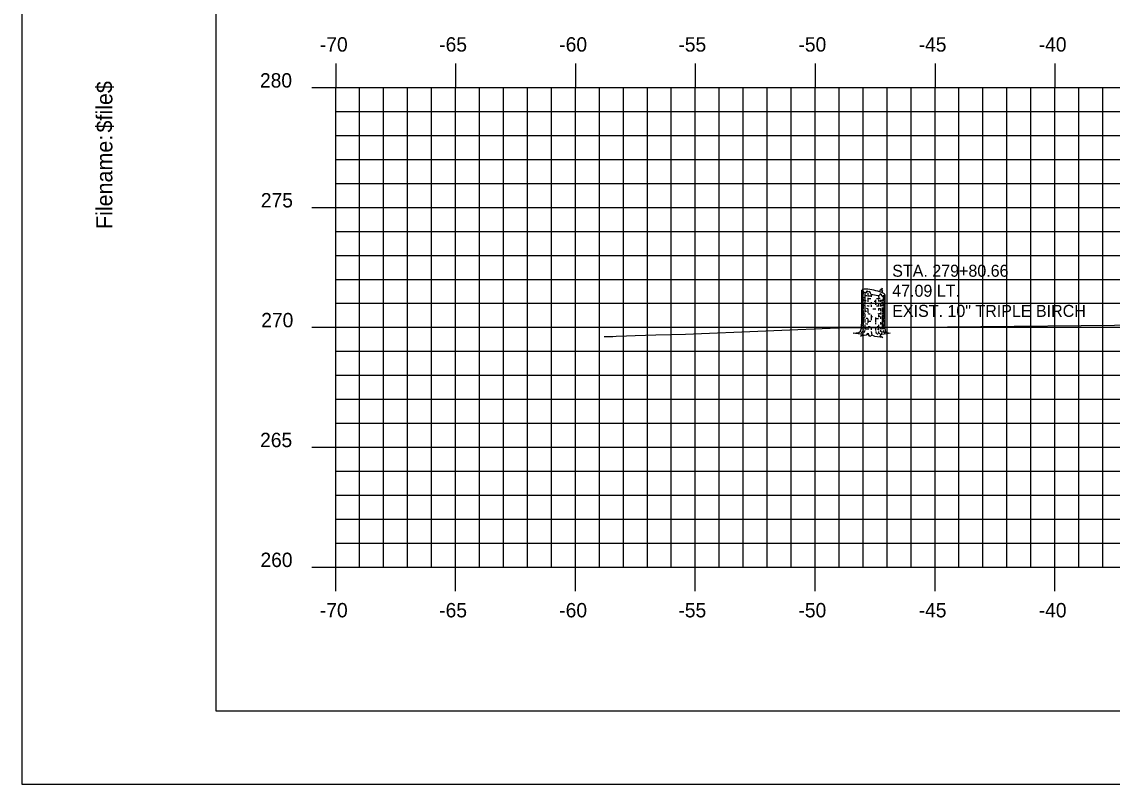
# Model space of a CAD drawing. Extents: x 855121 to 855291, y 366268 to 366378.
# Drawn here: x 855121.35 to 855166.83, y 366268.18 to 366299.98 of the extents above; entities that cross this region are included whole.
import ezdxf

# ---------------------------------------------------------------- set-up
doc = ezdxf.new("R2010")
doc.units = 0
for name, color, linetype in [('BORDER', 7, 'Continuous'), ('D_Text_Monospaced', 7, 'Continuous'), ('H_V ANNOTATION', 7, 'Continuous'), ('MAJOR', 7, 'Continuous'), ('MINOR', 7, 'Continuous'), ('PLOT BOUNDARY', 7, 'Continuous'), ('S_Roadway_Centerline', 7, 'Continuous'), ('S_Trees_Decid_NonPay', 7, 'Continuous')]:
    doc.layers.add(name, color=color, linetype=linetype)

msp = doc.modelspace()

# ---------------------------------------------------------------- linework, layer by layer
at = {"layer": 'BORDER'}
for p, q in [((855129.442, 366376.236), (855129.442, 366271.236)), ((855129.442, 366271.236), (855289.442, 366271.236))]:
    msp.add_line(p, q, dxfattribs=at)
at = {"layer": 'MAJOR'}
for p, q in [((855134.442, 366298.238), (855134.442, 366297.236)), ((855139.442, 366298.238), (855139.442, 366297.236)), ((855144.442, 366298.238), (855144.442, 366297.236)), ((855149.442, 366298.238), (855149.442, 366297.236)), ((855154.442, 366298.238), (855154.442, 366297.236)), ((855159.442, 366298.238), (855159.442, 366297.236)), ((855164.442, 366298.238), (855164.442, 366297.236)), ((855133.44, 366297.236), (855134.442, 366297.236)), ((855134.442, 366297.236), (855274.442, 366297.236)), ((855134.442, 366277.236), (855134.442, 366297.236)), ((855134.442, 366277.236), (855134.442, 366297.236)), ((855134.442, 366297.236), (855274.442, 366297.236)), ((855139.442, 366277.236), (855139.442, 366297.236)), ((855144.442, 366277.236), (855144.442, 366297.236)), ((855149.442, 366277.236), (855149.442, 366297.236)), ((855154.442, 366277.236), (855154.442, 366297.236)), ((855159.442, 366277.236), (855159.442, 366297.236)), ((855164.442, 366277.236), (855164.442, 366297.236)), ((855133.44, 366292.236), (855134.442, 366292.236)), ((855134.442, 366292.236), (855274.442, 366292.236)), ((855133.44, 366287.236), (855134.442, 366287.236)), ((855134.442, 366287.236), (855274.442, 366287.236)), ((855133.44, 366282.236), (855134.442, 366282.236)), ((855134.442, 366282.236), (855274.442, 366282.236)), ((855133.44, 366277.236), (855134.442, 366277.236)), ((855134.442, 366277.236), (855274.442, 366277.236)), ((855134.442, 366277.236), (855274.442, 366277.236)), ((855134.442, 366276.234), (855134.442, 366277.236)), ((855139.442, 366276.234), (855139.442, 366277.236)), ((855144.442, 366276.234), (855144.442, 366277.236)), ((855149.442, 366276.234), (855149.442, 366277.236)), ((855154.442, 366276.234), (855154.442, 366277.236)), ((855159.442, 366276.234), (855159.442, 366277.236)), ((855164.442, 366276.234), (855164.442, 366277.236))]:
    msp.add_line(p, q, dxfattribs=at)
at = {"layer": 'MINOR'}
for p, q in [((855134.442, 366277.236), (855134.442, 366297.236)), ((855135.442, 366277.236), (855135.442, 366297.236)), ((855136.442, 366277.236), (855136.442, 366297.236)), ((855137.442, 366277.236), (855137.442, 366297.236)), ((855138.442, 366277.236), (855138.442, 366297.236)), ((855140.442, 366277.236), (855140.442, 366297.236)), ((855141.442, 366277.236), (855141.442, 366297.236)), ((855142.442, 366277.236), (855142.442, 366297.236)), ((855143.442, 366277.236), (855143.442, 366297.236)), ((855145.442, 366277.236), (855145.442, 366297.236)), ((855146.442, 366277.236), (855146.442, 366297.236)), ((855147.442, 366277.236), (855147.442, 366297.236)), ((855148.442, 366277.236), (855148.442, 366297.236)), ((855150.442, 366277.236), (855150.442, 366297.236)), ((855151.442, 366277.236), (855151.442, 366297.236)), ((855152.442, 366277.236), (855152.442, 366297.236)), ((855153.442, 366277.236), (855153.442, 366297.236)), ((855155.442, 366277.236), (855155.442, 366297.236)), ((855156.442, 366277.236), (855156.442, 366297.236)), ((855157.442, 366277.236), (855157.442, 366297.236)), ((855158.442, 366277.236), (855158.442, 366297.236)), ((855160.442, 366277.236), (855160.442, 366297.236)), ((855161.442, 366277.236), (855161.442, 366297.236)), ((855162.442, 366277.236), (855162.442, 366297.236)), ((855163.442, 366277.236), (855163.442, 366297.236)), ((855165.442, 366277.236), (855165.442, 366297.236)), ((855166.442, 366277.236), (855166.442, 366297.236)), ((855134.442, 366296.236), (855274.442, 366296.236)), ((855134.442, 366296.236), (855135.444, 366296.236)), ((855134.442, 366295.236), (855274.442, 366295.236)), ((855134.442, 366295.236), (855135.444, 366295.236)), ((855134.442, 366294.236), (855274.442, 366294.236)), ((855134.442, 366294.236), (855135.444, 366294.236)), ((855134.442, 366293.236), (855274.442, 366293.236)), ((855134.442, 366293.236), (855135.444, 366293.236)), ((855134.442, 366291.236), (855274.442, 366291.236)), ((855134.442, 366291.236), (855135.444, 366291.236)), ((855134.442, 366290.236), (855274.442, 366290.236)), ((855134.442, 366290.236), (855135.444, 366290.236)), ((855134.442, 366289.236), (855274.442, 366289.236)), ((855134.442, 366289.236), (855135.444, 366289.236)), ((855134.442, 366288.236), (855274.442, 366288.236)), ((855134.442, 366288.236), (855135.444, 366288.236)), ((855134.442, 366286.236), (855274.442, 366286.236)), ((855134.442, 366286.236), (855135.444, 366286.236)), ((855134.442, 366285.236), (855274.442, 366285.236)), ((855134.442, 366285.236), (855135.444, 366285.236)), ((855134.442, 366284.236), (855274.442, 366284.236)), ((855134.442, 366284.236), (855135.444, 366284.236)), ((855134.442, 366283.236), (855274.442, 366283.236)), ((855134.442, 366283.236), (855135.444, 366283.236)), ((855134.442, 366281.236), (855274.442, 366281.236)), ((855134.442, 366281.236), (855135.444, 366281.236)), ((855134.442, 366280.236), (855274.442, 366280.236)), ((855134.442, 366280.236), (855135.444, 366280.236)), ((855134.442, 366279.236), (855274.442, 366279.236)), ((855134.442, 366279.236), (855135.444, 366279.236)), ((855134.442, 366278.236), (855274.442, 366278.236)), ((855134.442, 366278.236), (855135.444, 366278.236))]:
    msp.add_line(p, q, dxfattribs=at)
at = {"layer": 'PLOT BOUNDARY'}
msp.add_lwpolyline([(855121.349, 366268.177), (855291.349, 366268.177), (855291.349, 366378.177), (855121.349, 366378.177)], close=True, dxfattribs=at)
at = {"layer": 'S_Roadway_Centerline'}
msp.add_lwpolyline([(855145.639, 366286.847), (855145.792, 366286.851), (855146.004, 366286.857), (855146.141, 366286.862), (855146.573, 366286.879), (855146.934, 366286.894), (855147.8, 366286.924), (855149.04, 366286.949), (855155.731, 366287.224), (855156.269, 366287.225), (855156.866, 366287.226), (855157.182, 366287.226), (855171.097, 366287.369)], dxfattribs=at)
at = {"layer": 'S_Trees_Decid_NonPay'}
for p, q in [((855156.448, 366288.732), (855156.448, 366288.637)), ((855156.448, 366288.411), (855156.448, 366288.328)), ((855156.516, 366288.645), (855156.516, 366288.344)), ((855156.635, 366288.662), (855156.635, 366288.514)), ((855156.635, 366288.466), (855156.635, 366288.297)), ((855156.782, 366288.616), (855156.782, 366288.509)), ((855156.962, 366288.38), (855156.962, 366288.18)), ((855157.079, 366288.564), (855157.079, 366288.485)), ((855157.079, 366288.398), (855157.079, 366288.314)), ((855157.166, 366288.38), (855157.166, 366288.293)), ((855157.236, 366288.553), (855157.236, 366288.501)), ((855157.236, 366288.398), (855157.236, 366288.316)), ((855157.279, 366288.558), (855157.279, 366288.341)), ((855157.306, 366288.488), (855157.306, 366288.406)), ((855156.448, 366288.258), (855156.448, 366288.007)), ((855156.448, 366287.924), (855156.448, 366287.694)), ((855156.516, 366288.316), (855156.516, 366288.184)), ((855156.516, 366288.15), (855156.516, 366287.869)), ((855156.635, 366287.991), (855156.635, 366287.842)), ((855156.782, 366288.281), (855156.782, 366288.194)), ((855156.782, 366288.159), (855156.782, 366288.089)), ((855157.079, 366288.203), (855157.079, 366288.102)), ((855157.079, 366288.017), (855157.079, 366287.941)), ((855157.166, 366288.223), (855157.166, 366288.102)), ((855157.166, 366288.026), (855157.166, 366287.912)), ((855157.236, 366288.281), (855157.236, 366288.207)), ((855157.236, 366288.18), (855157.236, 366288.12)), ((855157.236, 366288.067), (855157.236, 366287.886)), ((855157.279, 366288.272), (855157.279, 366288.12)), ((855157.279, 366288.015), (855157.279, 366287.937)), ((855157.306, 366288.337), (855157.306, 366288.207)), ((855157.306, 366288.184), (855157.306, 366288.003)), ((855157.306, 366287.955), (855157.306, 366287.709)), ((855156.448, 366287.624), (855156.448, 366287.463)), ((855156.516, 366287.799), (855156.516, 366287.655)), ((855156.516, 366287.585), (855156.516, 366287.443)), ((855156.635, 366287.573), (855156.635, 366287.42)), ((855156.782, 366287.756), (855156.782, 366287.533)), ((855156.962, 366287.642), (855156.962, 366287.455)), ((855157.079, 366287.756), (855157.079, 366287.659)), ((855157.166, 366287.85), (855157.166, 366287.768)), ((855157.166, 366287.682), (855157.166, 366287.585)), ((855157.236, 366287.854), (855157.236, 366287.772)), ((855157.236, 366287.718), (855157.236, 366287.548)), ((855157.236, 366287.514), (855157.236, 366287.235)), ((855157.279, 366287.91), (855157.279, 366287.803)), ((855157.279, 366287.768), (855157.279, 366287.667)), ((855157.279, 366287.642), (855157.279, 366287.459)), ((855157.306, 366287.69), (855157.306, 366287.595)), ((855157.308, 366287.542), (855157.307, 366287.282)), ((855156.448, 366287.447), (855156.448, 366287.342)), ((855156.448, 366287.305), (855156.448, 366287.181)), ((855156.515, 366287.101), (855156.474, 366287.005)), ((855156.516, 366287.342), (855156.516, 366287.161)), ((855156.635, 366287.208), (855156.635, 366287.13)), ((855156.782, 366287.2), (855156.782, 366287.134)), ((855156.822, 366286.914), (855156.787, 366287.06)), ((855156.962, 366287.424), (855156.962, 366287.371)), ((855156.962, 366287.195), (855156.962, 366287.105)), ((855157.079, 366287.334), (855157.079, 366287.11)), ((855157.166, 366287.455), (855157.166, 366287.356)), ((855157.166, 366287.227), (855157.166, 366287.169)), ((855157.236, 366287.182), (855157.236, 366287.157)), ((855157.277, 366287.117), (855157.312, 366287.066)), ((855157.279, 366287.356), (855157.279, 366287.165)), ((855157.359, 366286.996), (855157.292, 366287.027)), ((855157.306, 366287.243), (855157.306, 366287.169))]:
    msp.add_line(p, q, dxfattribs=at)
for points in [[(855157.252, 366288.676), (855157.248, 366288.771), (855157.234, 366288.744), (855157.234, 366288.865), (855157.213, 366288.802), (855157.198, 366288.835), (855157.182, 366288.779), (855157.166, 366288.796), (855157.147, 366288.787), (855157.128, 366288.72)], [(855157.347, 366288.596), (855157.347, 366287.184), (855157.37, 366287.035), (855157.573, 366286.992), (855157.433, 366286.957), (855157.215, 366286.938), (855157.145, 366286.895), (855157.267, 366286.806), (855156.935, 366286.85), (855156.822, 366286.914), (855156.729, 366286.854), (855156.673, 366286.932), (855156.682, 366286.969), (855156.62, 366286.971), (855156.568, 366286.914), (855156.336, 366286.862), (855156.464, 366286.951), (855156.332, 366286.953), (855156.023, 366286.99), (855156.262, 366287.021), (855156.34, 366287.079), (855156.379, 366287.2), (855156.396, 366287.554), (855156.396, 366288.787)], [(855156.76, 366288.621), (855156.752, 366288.688), (855156.727, 366288.693), (855156.719, 366288.728), (855156.688, 366288.713), (855156.673, 366288.728), (855156.649, 366288.705), (855156.626, 366288.713), (855156.614, 366288.762), (855156.606, 366288.719), (855156.575, 366288.728), (855156.572, 366288.676)], [(855157.23, 366288.552), (855157.213, 366288.614), (855157.191, 366288.602), (855157.16, 366288.637), (855157.126, 366288.559)], [(855156.445, 366287.138), (855156.437, 366287.062), (855156.359, 366287.012)], [(855156.97, 366287.056), (855156.97, 366287.019), (855157.021, 366286.988), (855157.038, 366286.938)], [(855157.082, 366287.062), (855157.088, 366286.992), (855157.151, 366286.98)], [(855157.229, 366287.027), (855157.186, 366287.062), (855157.178, 366287.11)], [(855157.308, 366287.043), (855157.229, 366287.027), (855157.213, 366286.984)]]:
    msp.add_lwpolyline(points, dxfattribs=at)
for centre, radius, start, end in [((855156.527, 366288.509), 0.322, 86.0543, 108.1723), ((855156.377, 366286.329), 2.507, 78.1723, 86.0543), ((855156.415, 366288.64), 0.0191, 163.9485, 180), ((855156.415, 366288.64), 0.0191, 180, 196.0515), ((855156.415, 366288.426), 0.0191, 163.9485, 180), ((855156.415, 366288.426), 0.0191, 180, 196.0515), ((855156.414, 366288.787), 0.0179, 168.1723, 184.2278), ((855156.42, 366288.788), 0.0237, 184.2278, 198.1723), ((855156.42, 366288.642), 0.0252, 196.0515, 210), ((855156.42, 366288.428), 0.0252, 196.0515, 210), ((855156.414, 366288.787), 0.0179, 152.1168, 168.1723), ((855156.429, 366288.791), 0.0336, 198.1723, 216.9486), ((855156.419, 366288.785), 0.0237, 138.1723, 152.1168), ((855156.429, 366288.647), 0.0356, 210, 228.7494), ((855156.429, 366288.433), 0.0356, 210, 228.7494), ((855156.427, 366288.778), 0.0336, 119.396, 138.1723), ((855156.477, 366288.827), 0.0935, 216.9486, 228.1723), ((855156.471, 366288.694), 0.0984, 228.7494, 240), ((855156.471, 366288.48), 0.0984, 228.7494, 240), ((855156.456, 366288.726), 0.0935, 108.1723, 119.396), ((855156.629, 366288.997), 0.322, 228.1723, 250.2902), ((855156.585, 366288.891), 0.326, 240, 248.3243), ((855156.585, 366288.677), 0.326, 240, 243.5719), ((855156.585, 366288.778), 0.326, 240.9099, 257.8036), ((855156.585, 366288.677), 0.326, 250.4167, 261.8968), ((855156.585, 366288.891), 0.326, 257.8036, 261.8968), ((855157.366, 366291.054), 2.507, 250.2902, 251.5281), ((855156.871, 366290.901), 2.356, 261.8968, 263.2799), ((855156.871, 366290.788), 2.356, 264.242, 267.3673), ((855156.871, 366290.901), 2.356, 265.24, 267.8386), ((855157.366, 366291.054), 2.507, 255.9987, 258.1723), ((855157.366, 366291.054), 2.507, 258.1723, 264.5013), ((855156.377, 366286.329), 2.507, 70.2902, 78.1723), ((855156.871, 366290.788), 2.356, 273.1481, 276.7734), ((855157.114, 366288.386), 0.322, 48.1723, 70.2902), ((855157.216, 366288.874), 0.322, 272.4479, 288.1723), ((855157.157, 366288.778), 0.326, 291.9506, 300), ((855157.157, 366288.677), 0.326, 291.9506, 300), ((855157.287, 366288.657), 0.0935, 288.1723, 299.396), ((855157.271, 366288.581), 0.0984, 300, 311.2506), ((855157.271, 366288.48), 0.0984, 300, 311.2506), ((855157.266, 366288.556), 0.0935, 36.9486, 48.1723), ((855157.317, 366288.605), 0.0336, 299.396, 318.1723), ((855157.312, 366288.534), 0.0356, 311.2506, 330), ((855157.312, 366288.433), 0.0356, 311.2506, 330), ((855157.314, 366288.592), 0.0336, 18.1723, 36.9486), ((855157.324, 366288.599), 0.0237, 318.1723, 332.1168), ((855157.321, 366288.528), 0.0252, 330, 343.9485), ((855157.321, 366288.428), 0.0252, 330, 343.9485), ((855157.329, 366288.596), 0.0179, 332.1168, 348.1723), ((855157.323, 366288.595), 0.0237, 4.2278, 18.1723), ((855157.327, 366288.527), 0.0191, 360, 6.1128), ((855157.327, 366288.527), 0.0191, 343.9485, 360), ((855157.327, 366288.426), 0.0191, 360, 6.1128), ((855157.327, 366288.426), 0.0191, 343.9485, 360), ((855157.329, 366288.596), 0.0179, 348.1723, 4.2278), ((855156.415, 366288.323), 0.0191, 163.9485, 180), ((855156.415, 366288.323), 0.0191, 180, 196.0515), ((855156.415, 366288.103), 0.0191, 163.9485, 180), ((855156.415, 366288.103), 0.0191, 180, 196.0515), ((855156.42, 366288.325), 0.0252, 196.0515, 210), ((855156.42, 366288.105), 0.0252, 196.0515, 210), ((855156.415, 366287.988), 0.0191, 163.9485, 180), ((855156.415, 366287.988), 0.0191, 180, 196.0515), ((855156.421, 366287.99), 0.0252, 196.0515, 210), ((855156.429, 366288.33), 0.0356, 210, 228.7494), ((855156.429, 366288.11), 0.0356, 210, 228.7494), ((855156.43, 366287.995), 0.0356, 210, 228.7494), ((855156.471, 366288.377), 0.0984, 228.7494, 240), ((855156.471, 366288.157), 0.0984, 228.7494, 240), ((855156.472, 366288.043), 0.0984, 228.7494, 240), ((855156.585, 366288.574), 0.326, 240, 243.243), ((855156.585, 366288.354), 0.326, 240, 245.1545), ((855156.585, 366288.24), 0.326, 240, 247.8656), ((855156.585, 366288.469), 0.326, 245.1545, 257.8036), ((855156.585, 366288.574), 0.326, 251.6831, 257.8036), ((855156.585, 366288.24), 0.326, 257.6699, 261.8968), ((855156.871, 366290.687), 2.356, 261.8968, 262.5519), ((855156.872, 366290.25), 2.356, 261.8968, 262.8615), ((855156.871, 366290.364), 2.356, 262.6588, 264.7911), ((855156.871, 366290.479), 2.356, 263.2682, 265.6362), ((855156.871, 366290.584), 2.356, 263.3413, 264.9946), ((855156.871, 366290.584), 2.356, 266.5036, 267.8386), ((855156.871, 366290.364), 2.356, 269.5578, 270), ((855156.871, 366290.364), 2.356, 270, 272.414), ((855156.871, 366290.687), 2.356, 270.8119, 272.1981), ((855156.871, 366290.584), 2.356, 272.1981, 273.9741), ((855156.871, 366290.479), 2.356, 273.0067, 275.0647), ((855156.871, 366290.687), 2.356, 275.0647, 278.1032), ((855156.871, 366290.364), 2.356, 275.0647, 277.1868), ((855156.871, 366290.479), 2.356, 277.1868, 278.1032), ((855156.871, 366290.584), 2.356, 277.3838, 278.1032), ((855157.157, 366288.677), 0.326, 278.1032, 279.0854), ((855157.157, 366288.574), 0.326, 278.1032, 284.0382), ((855157.157, 366288.469), 0.326, 278.1032, 284.0382), ((855157.157, 366288.354), 0.326, 284.0382, 300), ((855157.158, 366288.24), 0.326, 283.9036, 291.8098), ((855157.157, 366288.469), 0.326, 291.9506, 300), ((855157.158, 366288.24), 0.326, 297.0058, 300), ((855157.271, 366288.272), 0.0984, 300, 311.2506), ((855157.271, 366288.157), 0.0984, 300, 311.2506), ((855157.272, 366288.043), 0.0984, 300, 311.2506), ((855157.312, 366288.225), 0.0356, 311.2506, 330), ((855157.312, 366288.11), 0.0356, 311.2506, 330), ((855157.313, 366287.995), 0.0356, 311.2506, 330), ((855157.321, 366288.22), 0.0252, 330, 343.9485), ((855157.321, 366288.105), 0.0252, 330, 343.9485), ((855157.322, 366287.99), 0.0252, 330, 343.9485), ((855157.327, 366288.323), 0.0191, 360, 6.1128), ((855157.327, 366288.323), 0.0191, 343.9485, 360), ((855157.327, 366288.218), 0.0191, 360, 6.1128), ((855157.327, 366288.218), 0.0191, 343.9485, 360), ((855157.327, 366288.103), 0.0191, 360, 6.1128), ((855157.327, 366288.103), 0.0191, 343.9485, 360), ((855157.328, 366287.988), 0.0191, 343.9485, 360), ((855157.328, 366287.988), 0.0191, 0, 6.1128), ((855156.41, 366287.464), 0.0191, 163.9485, 180), ((855156.41, 366287.464), 0.0191, 180, 196.0515), ((855156.416, 366287.466), 0.0252, 196.0515, 210), ((855156.412, 366287.888), 0.0191, 163.9485, 180), ((855156.415, 366287.783), 0.0191, 163.9485, 180), ((855156.415, 366287.783), 0.0191, 180, 196.0515), ((855156.42, 366287.785), 0.0252, 196.0515, 210), ((855156.429, 366287.79), 0.0356, 210, 228.7494), ((855156.471, 366287.838), 0.0984, 228.7494, 240), ((855156.582, 366288.14), 0.326, 240, 256.9079), ((855156.585, 366288.035), 0.326, 240, 245.1545), ((855156.585, 366287.944), 0.326, 241.939, 253.9183), ((855156.871, 366289.954), 2.356, 262.5843, 264.4865), ((855156.871, 366289.841), 2.356, 264.242, 267.469), ((855156.868, 366290.15), 2.356, 264.3443, 266.8529), ((855156.871, 366290.045), 2.356, 267.8386, 269.0054), ((855156.871, 366289.954), 2.356, 272.1981, 275.2726), ((855156.868, 366290.15), 2.356, 274.9734, 277.2455), ((855156.871, 366290.045), 2.356, 275.0647, 276.428), ((855157.157, 366288.035), 0.326, 284.0382, 291.9506), ((855157.157, 366287.831), 0.326, 284.0382, 291.9506), ((855157.155, 366288.14), 0.326, 292.4049, 300), ((855157.157, 366288.035), 0.326, 297.1525, 300), ((855157.269, 366287.942), 0.0984, 300, 311.2506), ((855157.271, 366287.838), 0.0984, 300, 311.2506), ((855157.31, 366287.895), 0.0356, 311.2506, 330), ((855157.312, 366287.79), 0.0356, 311.2506, 330), ((855157.317, 366287.466), 0.0252, 330, 343.9485), ((855157.319, 366287.89), 0.0252, 330, 343.9485), ((855157.323, 366287.464), 0.0191, 360, 6.1128), ((855157.323, 366287.464), 0.0191, 343.9485, 360), ((855157.325, 366287.888), 0.0191, 343.9485, 360), ((855157.321, 366287.785), 0.0252, 330, 343.9485), ((855157.325, 366287.888), 0.0191, 0, 6.1128), ((855157.327, 366287.783), 0.0191, 360, 6.1128), ((855157.327, 366287.783), 0.0191, 343.9485, 360), ((855157.327, 366287.693), 0.0191, 360, 6.1128), ((855156.4, 366287.244), 0.0191, 163.9485, 180), ((855156.4, 366287.244), 0.0191, 180, 196.0515), ((855156.406, 366287.245), 0.0252, 196.0515, 210), ((855156.415, 366287.25), 0.0356, 210, 228.7494), ((855156.406, 366287.354), 0.0191, 163.9485, 180), ((855156.406, 366287.354), 0.0191, 180, 196.0515), ((855156.411, 366287.356), 0.0252, 196.0515, 210), ((855156.421, 366287.361), 0.0356, 210, 228.7494), ((855156.456, 366287.298), 0.0984, 228.7494, 240), ((855156.425, 366287.471), 0.0356, 210, 228.7494), ((855156.462, 366287.408), 0.0984, 228.7494, 240), ((855156.467, 366287.519), 0.0984, 228.7494, 240), ((855156.57, 366287.495), 0.326, 240, 247.9161), ((855156.576, 366287.605), 0.326, 240, 241.9097), ((855156.581, 366287.716), 0.326, 240, 245.9375), ((855156.57, 366287.495), 0.326, 260.3834, 261.8968), ((855156.856, 366289.505), 2.356, 261.8968, 263.5333), ((855156.867, 366289.726), 2.356, 262.2226, 264.4852), ((855156.862, 366289.615), 2.356, 264.9089, 266.8158), ((855156.862, 366289.615), 2.356, 274.1864, 275.2829), ((855156.856, 366289.505), 2.356, 274.5551, 275.4167), ((855156.867, 366289.726), 2.356, 277.2863, 278.1032), ((855156.856, 366289.505), 2.356, 277.5403, 278.1032), ((855157.143, 366287.495), 0.326, 278.1032, 294.7094), ((855157.153, 366287.716), 0.326, 278.1032, 284.7741), ((855157.148, 366287.605), 0.326, 293.6544, 300), ((855157.256, 366287.298), 0.0984, 300, 311.2506), ((855157.267, 366287.519), 0.0984, 300, 311.2506), ((855157.298, 366287.25), 0.0356, 311.2506, 330), ((855157.307, 366287.245), 0.0252, 330, 343.9485), ((855157.313, 366287.244), 0.0191, 343.9485, 360), ((855157.308, 366287.471), 0.0356, 311.2506, 330), ((855157.313, 366287.244), 0.0191, 0, 6.1128)]:
    msp.add_arc(centre, radius, start, end, dxfattribs=at)

# ---------------------------------------------------------------- texts
at = {"layer": 'BORDER'}
for s, p in [('$file$', (855125.127, 366295.362)), ('Filename:', (855125.127, 366291.335))]:
    msp.add_text(s, height=0.6696, rotation=90, dxfattribs=at).set_placement(p)
at = {"layer": 'D_Text_Monospaced'}
for s, height, p in [('STA. 279+80.66', 0.49998, (855157.657, 366289.345)), ('47.09 LT.', 0.5, (855157.657, 366288.511)), ('EXIST. 10" TRIPLE BIRCH', 0.49998, (855157.657, 366287.671))]:
    msp.add_text(s, height=height, dxfattribs=at).set_placement(p)
at = {"layer": 'H_V ANNOTATION'}
for s, p in [('-70', (855133.783, 366298.736)), ('-65', (855138.76, 366298.736)), ('-60', (855143.768, 366298.736)), ('-55', (855148.738, 366298.736)), ('-50', (855153.746, 366298.736)), ('-45', (855158.76, 366298.736)), ('-40', (855163.768, 366298.736)), ('280', (855131.283, 366297.236)), ('275', (855131.32, 366292.236)), ('270', (855131.336, 366287.236)), ('265', (855131.288, 366282.236)), ('260', (855131.304, 366277.236)), ('-70', (855133.783, 366275.136)), ('-65', (855138.76, 366275.136)), ('-60', (855143.768, 366275.136)), ('-55', (855148.738, 366275.136)), ('-50', (855153.746, 366275.136)), ('-45', (855158.76, 366275.136)), ('-40', (855163.768, 366275.136))]:
    msp.add_text(s, height=0.6, dxfattribs=at).set_placement(p)

doc.saveas('drawing.dxf')
